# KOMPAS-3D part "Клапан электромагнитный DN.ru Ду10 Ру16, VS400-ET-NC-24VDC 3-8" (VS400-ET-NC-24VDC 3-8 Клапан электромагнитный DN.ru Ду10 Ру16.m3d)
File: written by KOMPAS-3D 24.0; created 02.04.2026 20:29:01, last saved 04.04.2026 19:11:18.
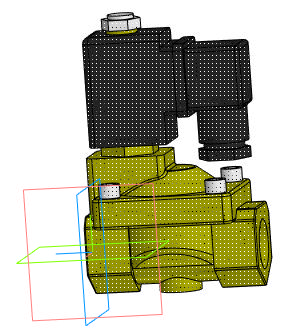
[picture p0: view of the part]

Document properties: Автор: artio; Полное имя файла: ..\VS400-ET-NC-24VDC 3-8 Клапан электромагнитный DN.ru Ду10 Ру16.cdw

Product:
- Body: Тело 1  | qty 1
    Масса: 1.030062
- Part/product: Клапан электромагнитный DN.ru Ду10 Ру16  | designation VS400-ET-NC-24VDC 3-8
    Масса: 0.797
    Раздел спецификации: Прочие изделия
    Форматы листов документа: A3
    Примечание: D130-04718
    additional columns: ef56311e-7521-43dc-8291-0e6108b3d81d; VS400-ET-NC-220VAC 3-8; artio; c; Шероховатость не задана; Да

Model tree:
1. Операция без истории:1

Expressions: VS400-ET-NC-24VDC 3-8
